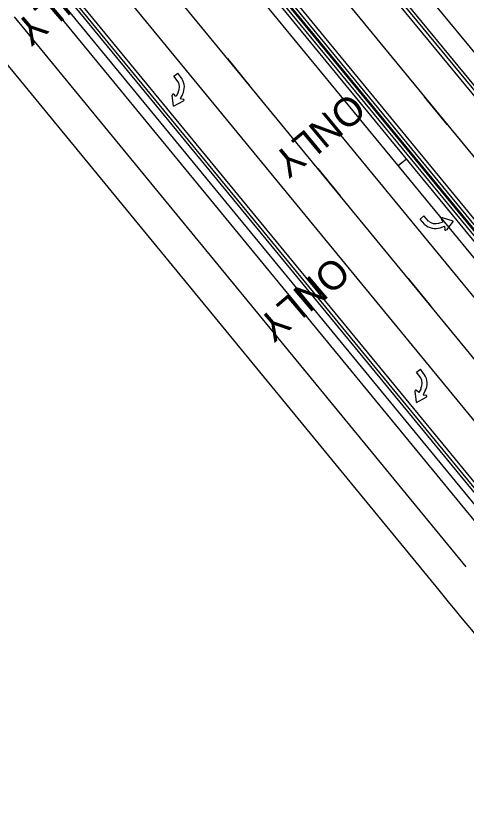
# Model space of a CAD drawing. Extents: x 2252205 to 2259955, y 13788514 to 13798103.
# Drawn here: x 2256095.8 to 2256222.6, y 13792290.9 to 13792511.8 of the extents above; entities that cross this region are included whole.
import ezdxf

# ---------------------------------------------------------------- set-up
doc = ezdxf.new("R2010")
doc.units = 0
for name, color, linetype in [('GEOM_CENTERLINE_ALIGN', 7, 'Continuous'), ('GEOM_CENTERLINE_STA_100', 7, 'Continuous'), ('GEOM_CENTERLINE_STA_50', 7, 'Continuous'), ('ROAD_BIKE_SHARED_USE', 7, 'Continuous'), ('Road_Curb_Back', 7, 'Continuous'), ('Road_Curb_Face', 7, 'Continuous'), ('Road_EdgeOfPavementInside', 7, 'Continuous'), ('Road_EdgeOfPavementOutside', 7, 'Continuous'), ('ROAD_ROW_EXIST', 7, 'Continuous'), ('ROAD_ROW_PROPOSED', 7, 'Continuous'), ('Road_Sidewalk_Back', 7, 'Continuous'), ('TRAF_PAVMRK_W_4IN_BRK', 7, 'Continuous'), ('TRAF_PAVMRK_W_4IN_SLD', 7, 'Continuous'), ('TRAF_PAVMRK_W_8IN_SLD', 7, 'Continuous'), ('TRAF_PAVMRK_W_LT_TRN_ARROW_WORD', 7, 'Continuous'), ('TRAF_PAVMRK_W_RT_TRN_ARROW_WORD', 7, 'Continuous'), ('TRAF_PAVMRK_Y_4IN_SLD', 7, 'Continuous')]:
    doc.layers.add(name, color=color, linetype=linetype)

msp = doc.modelspace()

# ---------------------------------------------------------------- linework, layer by layer
at = {"layer": 'GEOM_CENTERLINE_ALIGN'}
msp.add_line((2256266.48, 13792392.92), (2254123.79, 13794999.75), dxfattribs=at)
at = {"layer": 'GEOM_CENTERLINE_STA_100'}
msp.add_line((2256203.4, 13792469.66), (2256205.72, 13792471.57), dxfattribs=at)
at = {"layer": 'GEOM_CENTERLINE_STA_50'}
msp.add_line((2256203.4, 13792469.66), (2256204.56, 13792470.62), dxfattribs=at)
at = {"layer": 'ROAD_BIKE_SHARED_USE'}
for p, q in [((2256230.3, 13792363.19), (2256103.52, 13792517.43)), ((2256222.57, 13792356.84), (2256095.45, 13792511.5))]:
    msp.add_line(p, q, dxfattribs=at)
at = {"layer": 'Road_Curb_Back'}
for p, q in [((2256290.3, 13792412.5), (2256064.18, 13792687.6)), ((2256270.47, 13792396.2), (2256080.4, 13792627.45)), ((2256270.21, 13792395.99), (2256143.53, 13792550.11)), ((2256234.16, 13792366.36), (2256107.56, 13792520.39))]:
    msp.add_line(p, q, dxfattribs=at)
at = {"layer": 'Road_Curb_Face'}
for p, q in [((2256289.65, 13792411.97), (2256063.58, 13792687.02)), ((2256234.8, 13792366.89), (2256108.23, 13792520.88))]:
    msp.add_line(p, q, dxfattribs=at)
at = {"layer": 'Road_EdgeOfPavementInside'}
for p, q in [((2256271.11, 13792396.73), (2256081.04, 13792627.98)), ((2256269.57, 13792395.46), (2256142.99, 13792549.46))]:
    msp.add_line(p, q, dxfattribs=at)
at = {"layer": 'Road_EdgeOfPavementOutside'}
for p, q in [((2256289.65, 13792411.97), (2256063.58, 13792687.02)), ((2256234.8, 13792366.89), (2256108.23, 13792520.88))]:
    msp.add_line(p, q, dxfattribs=at)
at = {"layer": 'ROAD_ROW_EXIST'}
msp.add_line((2256265.67, 13792324.77), (2256010.41, 13792635.34), dxfattribs=at)
at = {"layer": 'ROAD_ROW_PROPOSED'}
msp.add_line((2256088.39, 13792504.08), (2256214.83, 13792350.25), dxfattribs=at)
msp.add_arc((2265116.02, 13799666.6), 11522.16, 219.418553, 219.801534, dxfattribs=at)
at = {"layer": 'Road_Sidewalk_Back'}
msp.add_line((2256294.93, 13792416.31), (2256068.49, 13792691.8), dxfattribs=at)
at = {"layer": 'TRAF_PAVMRK_W_4IN_BRK'}
for p, q in [((2256052.59, 13792681.49), (2256280.38, 13792404.35)), ((2256252.57, 13792381.49), (2256024.81, 13792658.59))]:
    msp.add_line(p, q, dxfattribs=at)
for points in [[(2256155.36, 13792499.77), (2256155.36, 13792499.76)], [(2256155.36, 13792499.76), (2256161.71, 13792492.03)], [(2256217.17, 13792481.26), (2256210.82, 13792488.98)], [(2256217.18, 13792481.25), (2256217.17, 13792481.26)], [(2256180.76, 13792468.86), (2256180.77, 13792468.85)], [(2256180.77, 13792468.85), (2256187.12, 13792461.13)], [(2256206.17, 13792437.95), (2256206.17, 13792437.94)], [(2256206.17, 13792437.94), (2256212.52, 13792430.22)]]:
    msp.add_lwpolyline(points, dxfattribs=at)
at = {"layer": 'TRAF_PAVMRK_W_4IN_SLD'}
for p, q in [((2256288.88, 13792411.34), (2256061.08, 13792688.49)), ((2256235.58, 13792367.52), (2256109.04, 13792521.48))]:
    msp.add_line(p, q, dxfattribs=at)
at = {"layer": 'TRAF_PAVMRK_W_8IN_SLD'}
for p, q in [((2256244.07, 13792374.51), (2256117.53, 13792528.46)), ((2256261.07, 13792388.48), (2256182.12, 13792484.53))]:
    msp.add_line(p, q, dxfattribs=at)
at = {"layer": 'TRAF_PAVMRK_W_LT_TRN_ARROW_WORD'}
for p, q in [((2256210.59, 13792455.53), (2256209.56, 13792454.59)), ((2256210.88, 13792453.15), (2256209.56, 13792454.59)), ((2256211.9, 13792454.06), (2256210.59, 13792455.53)), ((2256210.59, 13792455.53), (2256210.59, 13792455.53)), ((2256216.07, 13792453.92), (2256215.6, 13792454.6)), ((2256218.91, 13792454.09), (2256215.91, 13792455.02)), ((2256218.92, 13792454.09), (2256216.96, 13792451.62)), ((2256214.81, 13792453.49), (2256216.09, 13792453.9)), ((2256215.24, 13792452.22), (2256216.48, 13792452.62)), ((2256216.48, 13792452.62), (2256216.49, 13792451.78))]:
    msp.add_line(p, q, dxfattribs=at)
for centre, radius, start, end in [((2256213.86, 13792456.42), 3.06, 230.3673, 288.148), ((2256215.82, 13792454.77), 0.274, 72.8003, 215.0633), ((2256213.86, 13792456.42), 4.42, 227.616, 288.1932), ((2256216.75, 13792451.79), 0.274, 179.7381, 322.0012)]:
    msp.add_arc(centre, radius, start, end, dxfattribs=at)
at = {"layer": 'TRAF_PAVMRK_W_RT_TRN_ARROW_WORD'}
for p, q in [((2256140.26, 13792494.83), (2256141.36, 13792495.67)), ((2256141.48, 13792493.28), (2256140.26, 13792494.83)), ((2256140.26, 13792494.83), (2256140.26, 13792494.83)), ((2256142.55, 13792494.13), (2256141.36, 13792495.67)), ((2256140.23, 13792486.38), (2256139.84, 13792489.5)), ((2256140.89, 13792489.15), (2256140.3, 13792489.72)), ((2256141.54, 13792490.32), (2256140.91, 13792489.13)), ((2256142.72, 13792489.67), (2256142.1, 13792488.52)), ((2256140.23, 13792486.37), (2256143, 13792487.87)), ((2256142.1, 13792488.52), (2256142.93, 13792488.37)), ((2256208.56, 13792411.56), (2256209.66, 13792412.4)), ((2256210.85, 13792410.85), (2256209.66, 13792412.4)), ((2256209.78, 13792410), (2256208.56, 13792411.56)), ((2256208.56, 13792411.56), (2256208.56, 13792411.56)), ((2256208.53, 13792403.11), (2256208.14, 13792406.23)), ((2256209.19, 13792405.88), (2256208.6, 13792406.45)), ((2256209.84, 13792407.04), (2256209.21, 13792405.85)), ((2256211.02, 13792406.4), (2256210.41, 13792405.24)), ((2256208.53, 13792403.1), (2256211.3, 13792404.6)), ((2256210.41, 13792405.24), (2256211.23, 13792405.09))]:
    msp.add_line(p, q, dxfattribs=at)
for centre, radius, start, end in [((2256138.82, 13792491.76), 4.42, 331.8386, 32.4158), ((2256138.82, 13792491.76), 3.06, 331.8837, 29.6645), ((2256140.1, 13792489.54), 0.274, 44.9684, 187.2315), ((2256142.88, 13792488.11), 0.274, 298.0306, 80.2936), ((2256207.12, 13792408.49), 3.06, 331.8837, 29.6645), ((2256207.12, 13792408.49), 4.42, 331.8386, 32.4158), ((2256208.4, 13792406.27), 0.274, 44.9684, 187.2315), ((2256211.18, 13792404.83), 0.274, 298.0306, 80.2936)]:
    msp.add_arc(centre, radius, start, end, dxfattribs=at)
at = {"layer": 'TRAF_PAVMRK_Y_4IN_SLD'}
for p, q in [((2256271.88, 13792397.37), (2256044.1, 13792674.49)), ((2256268.79, 13792394.83), (2256142.34, 13792548.67))]:
    msp.add_line(p, q, dxfattribs=at)

# ---------------------------------------------------------------- texts
at = {"layer": 'TRAF_PAVMRK_W_LT_TRN_ARROW_WORD'}
msp.add_text('ONLY', height=8, rotation=219.6587, dxfattribs=at).set_placement((2256189.9, 13792490.53))
at = {"layer": 'TRAF_PAVMRK_W_RT_TRN_ARROW_WORD'}
for p in [(2256117.12, 13792527.85), (2256185.42, 13792444.58)]:
    msp.add_text('ONLY', height=8, rotation=220.3731, dxfattribs=at).set_placement(p)

doc.saveas('drawing.dxf')
